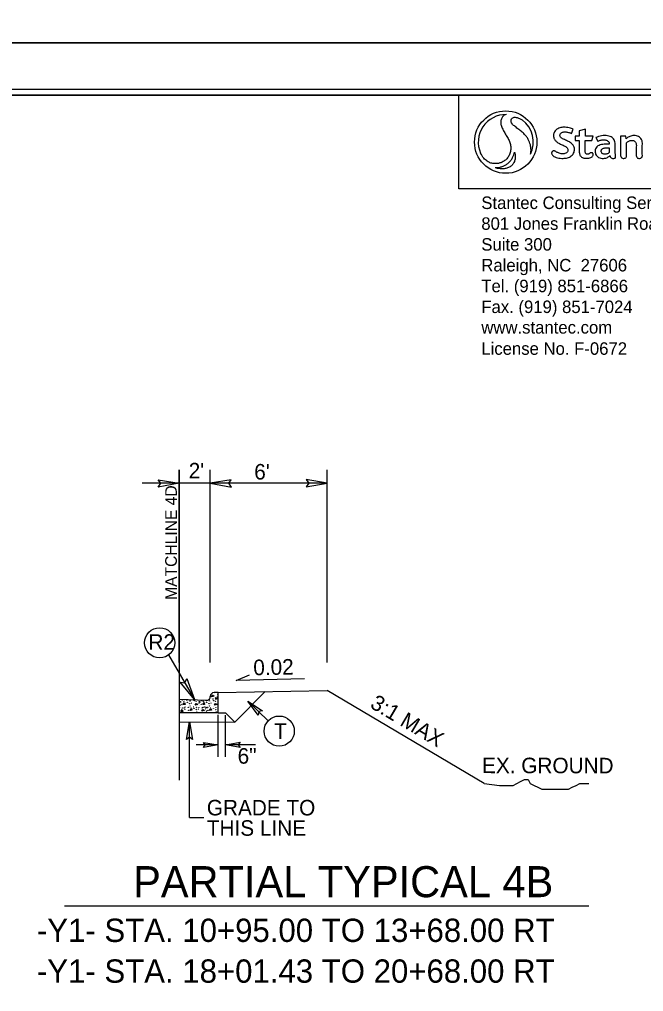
# Model space of a CAD drawing. Extents: x 2320980 to 2456309, y 595047 to 606177.
# Drawn here: x 2455941.7 to 2455995.1, y 596660.3 to 596743.6 of the extents above; entities that cross this region are included whole.
import ezdxf

# ---------------------------------------------------------------- set-up
doc = ezdxf.new("R2010")
doc.units = 0
for name, color, linetype in [('Matchline', 7, 'Continuous'), ('Matchline Text', 7, 'Continuous'), ('Old_Level_1', 7, 'Continuous'), ('Old_Level_2', 7, 'Continuous'), ('Old_Level_20', 7, 'Continuous'), ('Old_Level_21', 7, 'Continuous'), ('Old_Level_3', 7, 'Continuous'), ('Prop Dimension Text', 7, 'Continuous'), ('Scratch_Level_0', 7, 'Continuous'), ('Sheet Data Text CELL', 7, 'Continuous'), ('Sheet Plan CELL', 7, 'Continuous'), ('Sheet Plot Border Inside CELL', 7, 'Continuous'), ('Sheet Plot Border Outside CELL', 7, 'Continuous'), ('Typical Berm CELL', 7, 'Continuous'), ('Typical Curb CELL', 7, 'Continuous'), ('Typical Hinge Slope Arterial CELL', 7, 'Continuous'), ('Typical ID Circle CELL', 7, 'Continuous'), ('Typical Pavement Slope CELL', 7, 'Continuous'), ('Typical Terminator CELL', 7, 'Continuous')]:
    doc.layers.add(name, color=color, linetype=linetype)

msp = doc.modelspace()

# ---------------------------------------------------------------- linework, layer by layer
at = {"layer": 'Matchline'}
msp.add_line((2455955.368, 596705.007), (2455955.368, 596678.433), dxfattribs=at)
at = {"layer": 'Old_Level_21'}
for p, q in [((2455955.368, 596688.514), (2455955.368, 596705.007)), ((2455958.028, 596688.514), (2455958.028, 596705.007)), ((2455968.028, 596688.514), (2455968.028, 596705.007)), ((2455955.368, 596703.855), (2455952.191, 596703.855)), ((2455968.028, 596703.855), (2455955.368, 596703.855)), ((2455981.492, 596678.15), (2455968.028, 596686.124)), ((2455958.693, 596680.445), (2455958.693, 596684.035)), ((2455959.326, 596680.445), (2455959.326, 596683.989)), ((2455956.236, 596675.229), (2455957.475, 596675.229))]:
    msp.add_line(p, q, dxfattribs=at)
at = {"layer": 'Old_Level_3'}
msp.add_line((2455945.536, 596667.68), (2455990.456, 596667.68), dxfattribs=at)
at = {"layer": 'Prop Dimension Text'}
for p, q in [((2455962.993, 596683.528), (2455961.234, 596685.209)), ((2455956.236, 596675.229), (2455956.236, 596683.418)), ((2455958.693, 596681.457), (2455956.806, 596681.457)), ((2455961.888, 596681.457), (2455959.326, 596681.457))]:
    msp.add_line(p, q, dxfattribs=at)
msp.add_lwpolyline([(2455966.091, 596687.116), (2455960.235, 596686.955), (2455961.372, 596687.444)], dxfattribs=at)
for centre in [(2455953.687, 596690.196), (2455963.927, 596682.635)]:
    msp.add_circle(centre, 1.293, dxfattribs=at)
at = {"layer": 'Scratch_Level_0'}
msp.add_lwpolyline([(2455979.323, 596737.076), (2456002.097, 596737.079), (2456002.098, 596729.07), (2455979.324, 596729.067)], close=True, dxfattribs=at)
at = {"layer": 'Sheet Data Text CELL'}
for p, q in [((2455988.965, 596733.819), (2455989.095, 596734.192)), ((2455990.145, 596734.169), (2455989.619, 596734.022)), ((2455990.145, 596733.585), (2455990.145, 596734.169)), ((2455989.619, 596733.585), (2455989.285, 596733.585)), ((2455989.285, 596733.585), (2455989.285, 596733.219)), ((2455989.619, 596734.022), (2455989.619, 596733.585)), ((2455990.826, 596733.585), (2455990.145, 596733.585)), ((2455990.699, 596733.219), (2455990.826, 596733.585)), ((2455991.046, 596733.451), (2455991.206, 596733.141)), ((2455993.606, 596733.584), (2455993.163, 596733.584)), ((2455993.163, 596733.584), (2455993.163, 596731.906)), ((2455993.635, 596733.362), (2455993.606, 596733.584)), ((2455989.285, 596733.219), (2455989.623, 596733.219)), ((2455990.135, 596732.294), (2455990.142, 596733.219)), ((2455990.142, 596733.219), (2455990.699, 596733.219)), ((2455992.195, 596732.591), (2455992.196, 596732.176)), ((2455993.679, 596731.906), (2455993.679, 596733.014))]:
    msp.add_line(p, q, dxfattribs=at)
for points in [[(2455983.379, 596735.428), (2455983.379, 596735.428)], [(2455984.732, 596734.965), (2455984.732, 596734.965)]]:
    msp.add_lwpolyline(points, dxfattribs=at)
msp.add_circle((2455983.328, 596733.072), 2.673, dxfattribs=at)
for start, end in [(88.77376, 203.69163), (88.76731, 88.77376), (333.78865, 53.43978), (247.12556, 251.46513)]:
    msp.add_arc((2455983.328, 596733.072), 2.357, start, end, dxfattribs=at)
for points, degree in [([(2455983.379, 596735.428), (2455983.322, 596735.416), (2455983.188, 596735.388), (2455983.013, 596735.209), (2455982.883, 596734.916), (2455982.9, 596734.587), (2455983.016, 596734.269), (2455983.192, 596733.96), (2455983.374, 596733.619), (2455983.576, 596733.297), (2455983.716, 596732.97), (2455983.782, 596732.614), (2455983.739, 596732.258), (2455983.635, 596731.931), (2455983.434, 596731.634), (2455983.17, 596731.423), (2455982.894, 596731.299), (2455982.644, 596731.222), (2455982.365, 596731.222), (2455982.055, 596731.265), (2455981.749, 596731.405), (2455981.423, 596731.681), (2455981.266, 596731.952), (2455981.17, 596732.125)], 3), ([(2455983.379, 596735.428), (2455983.379, 596735.428), (2455983.379, 596735.428), (2455983.379, 596735.428)], 2), ([(2455985.442, 596732.031), (2455985.463, 596732.114), (2455985.498, 596732.269), (2455985.491, 596732.518), (2455985.467, 596732.737), (2455985.403, 596732.94), (2455985.327, 596733.175), (2455985.194, 596733.43), (2455985.004, 596733.67), (2455984.756, 596733.923), (2455984.446, 596734.148), (2455984.127, 596734.409), (2455983.871, 596734.601), (2455983.781, 596734.827), (2455983.78, 596734.999), (2455983.865, 596735.115), (2455983.978, 596735.196), (2455984.129, 596735.21), (2455984.307, 596735.176), (2455984.513, 596735.089), (2455984.655, 596735.009), (2455984.732, 596734.965)], 3), ([(2455989.095, 596734.192), (2455989.072, 596734.203), (2455988.968, 596734.253), (2455988.77, 596734.305), (2455988.527, 596734.335), (2455988.306, 596734.346), (2455988.121, 596734.328), (2455987.945, 596734.291), (2455987.775, 596734.224), (2455987.611, 596734.111), (2455987.493, 596733.961), (2455987.426, 596733.809), (2455987.411, 596733.667), (2455987.418, 596733.536), (2455987.446, 596733.411), (2455987.499, 596733.308), (2455987.563, 596733.215), (2455987.642, 596733.13), (2455987.738, 596733.053), (2455987.856, 596732.982), (2455988.003, 596732.906), (2455988.165, 596732.832), (2455988.33, 596732.762), (2455988.466, 596732.692), (2455988.566, 596732.607), (2455988.635, 596732.527), (2455988.659, 596732.429), (2455988.656, 596732.336), (2455988.618, 596732.233), (2455988.533, 596732.148), (2455988.398, 596732.09), (2455988.238, 596732.066), (2455988.06, 596732.074), (2455987.903, 596732.107), (2455987.776, 596732.17), (2455987.673, 596732.212), (2455987.604, 596732.277), (2455987.538, 596732.302), (2455987.478, 596732.328), (2455987.413, 596732.324), (2455987.348, 596732.304), (2455987.293, 596732.256), (2455987.257, 596732.188), (2455987.254, 596732.113), (2455987.265, 596732.039), (2455987.323, 596731.961), (2455987.435, 596731.849), (2455987.633, 596731.752), (2455987.878, 596731.687), (2455988.127, 596731.674), (2455988.341, 596731.68), (2455988.528, 596731.704), (2455988.692, 596731.754), (2455988.863, 596731.831), (2455989.027, 596731.96), (2455989.154, 596732.12), (2455989.208, 596732.309), (2455989.215, 596732.479), (2455989.194, 596732.633), (2455989.133, 596732.757), (2455989.06, 596732.881), (2455988.932, 596732.986), (2455988.787, 596733.083), (2455988.627, 596733.16), (2455988.454, 596733.241), (2455988.274, 596733.318), (2455988.121, 596733.399), (2455988.018, 596733.492), (2455987.974, 596733.583), (2455987.966, 596733.678), (2455987.994, 596733.765), (2455988.053, 596733.841), (2455988.135, 596733.895), (2455988.243, 596733.934), (2455988.372, 596733.944), (2455988.5, 596733.939), (2455988.627, 596733.919), (2455988.75, 596733.892), (2455988.865, 596733.858), (2455988.934, 596733.831), (2455988.965, 596733.819)], 3), ([(2455992.247, 596731.915), (2455992.248, 596731.897), (2455992.252, 596731.854), (2455992.295, 596731.79), (2455992.357, 596731.718), (2455992.469, 596731.666), (2455992.587, 596731.67), (2455992.697, 596731.694), (2455992.74, 596731.781), (2455992.742, 596731.868), (2455992.717, 596731.985), (2455992.69, 596732.307), (2455992.71, 596732.647), (2455992.704, 596733.015), (2455992.662, 596733.193), (2455992.562, 596733.353), (2455992.454, 596733.476), (2455992.276, 596733.566), (2455992.056, 596733.623), (2455991.795, 596733.64), (2455991.531, 596733.614), (2455991.277, 596733.555), (2455991.121, 596733.485), (2455991.046, 596733.451)], 3), ([(2455993.679, 596733.014), (2455993.687, 596733.022), (2455993.723, 596733.055), (2455993.809, 596733.107), (2455993.921, 596733.181), (2455994.063, 596733.224), (2455994.207, 596733.223), (2455994.346, 596733.178), (2455994.441, 596733.079), (2455994.493, 596732.961), (2455994.52, 596732.801), (2455994.503, 596732.562), (2455994.515, 596732.259), (2455994.499, 596732.006), (2455994.51, 596731.832), (2455994.57, 596731.738), (2455994.675, 596731.672), (2455994.797, 596731.674), (2455994.913, 596731.702), (2455995.008, 596731.774), (2455995.035, 596731.912), (2455995.015, 596732.156), (2455995.028, 596732.456), (2455995.021, 596732.786), (2455995.033, 596732.996), (2455995.005, 596733.178), (2455994.948, 596733.306), (2455994.857, 596733.437), (2455994.711, 596733.54), (2455994.527, 596733.627), (2455994.317, 596733.632), (2455994.128, 596733.621), (2455993.958, 596733.565), (2455993.807, 596733.495), (2455993.706, 596733.415), (2455993.653, 596733.375), (2455993.635, 596733.362)], 3), ([(2455989.623, 596733.219), (2455989.621, 596732.892), (2455989.62, 596732.547), (2455989.624, 596732.162), (2455989.641, 596732.07), (2455989.677, 596731.944), (2455989.749, 596731.858), (2455989.821, 596731.791), (2455989.898, 596731.74), (2455990.02, 596731.698), (2455990.188, 596731.679), (2455990.362, 596731.687), (2455990.536, 596731.711), (2455990.668, 596731.778), (2455990.765, 596731.856), (2455990.81, 596731.946), (2455990.815, 596732.025), (2455990.801, 596732.092), (2455990.766, 596732.131), (2455990.724, 596732.156), (2455990.675, 596732.165), (2455990.623, 596732.166), (2455990.57, 596732.152), (2455990.523, 596732.114), (2455990.47, 596732.074), (2455990.405, 596732.046), (2455990.336, 596732.024), (2455990.264, 596732.032), (2455990.202, 596732.066), (2455990.154, 596732.114), (2455990.133, 596732.197), (2455990.134, 596732.256), (2455990.135, 596732.294)], 3), ([(2455992.194, 596732.901), (2455992.16, 596732.9), (2455992.05, 596732.898), (2455991.859, 596732.889), (2455991.632, 596732.877), (2455991.42, 596732.83), (2455991.224, 596732.749), (2455991.053, 596732.602), (2455990.973, 596732.394), (2455990.984, 596732.198), (2455991.016, 596732.03), (2455991.118, 596731.888), (2455991.266, 596731.758), (2455991.478, 596731.679), (2455991.698, 596731.676), (2455991.902, 596731.702), (2455992.057, 596731.757), (2455992.172, 596731.835), (2455992.22, 596731.887), (2455992.247, 596731.915)], 3), ([(2455991.206, 596733.141), (2455991.23, 596733.154), (2455991.303, 596733.193), (2455991.422, 596733.23), (2455991.566, 596733.267), (2455991.702, 596733.276), (2455991.844, 596733.271), (2455991.972, 596733.231), (2455992.083, 596733.167), (2455992.161, 596733.074), (2455992.194, 596732.979), (2455992.194, 596732.92), (2455992.194, 596732.901)], 3), ([(2455992.196, 596732.176), (2455992.183, 596732.165), (2455992.134, 596732.128), (2455992.045, 596732.08), (2455991.92, 596732.028), (2455991.787, 596732.02), (2455991.672, 596732.05), (2455991.592, 596732.102), (2455991.54, 596732.163), (2455991.505, 596732.237), (2455991.5, 596732.316), (2455991.515, 596732.395), (2455991.562, 596732.47), (2455991.643, 596732.518), (2455991.739, 596732.561), (2455991.866, 596732.578), (2455991.996, 596732.585), (2455992.111, 596732.592), (2455992.171, 596732.591), (2455992.195, 596732.591)], 3), ([(2455982.412, 596730.901), (2455982.47, 596730.895), (2455982.606, 596730.882), (2455982.84, 596730.927), (2455983.101, 596730.988), (2455983.336, 596731.125), (2455983.552, 596731.277), (2455983.755, 596731.495), (2455983.923, 596731.737), (2455984.03, 596731.99), (2455984.062, 596732.139), (2455984.078, 596732.21)], 3), ([(2455984.078, 596732.21), (2455984.095, 596732.15), (2455984.139, 596731.997), (2455984.15, 596731.741), (2455984.106, 596731.463), (2455983.963, 596731.211), (2455983.771, 596730.979), (2455983.491, 596730.852), (2455983.194, 596730.784), (2455982.888, 596730.779), (2455982.679, 596730.819), (2455982.579, 596730.838)], 3), ([(2455993.163, 596731.906), (2455993.168, 596731.884), (2455993.179, 596731.834), (2455993.216, 596731.749), (2455993.31, 596731.677), (2455993.441, 596731.676), (2455993.573, 596731.686), (2455993.651, 596731.772), (2455993.679, 596731.847), (2455993.679, 596731.888), (2455993.679, 596731.906)], 3)]:
    msp.add_open_spline(points, degree=degree, dxfattribs=at)
at = {"layer": 'Sheet Plan CELL'}
for points in [[(2455742.104, 596527.076), (2455742.099, 596737.071), (2456002.097, 596737.079), (2456002.099, 596707.066), (2456042.107, 596707.064), (2456042.107, 596527.076)], [(2456042.112, 596737.076), (2455742.104, 596737.076), (2455742.104, 596527.076), (2456042.107, 596527.076)]]:
    msp.add_lwpolyline(points, close=True, dxfattribs=at)
at = {"layer": 'Sheet Plot Border Inside CELL'}
msp.add_lwpolyline([(2455711.407, 596526.574), (2456044.604, 596526.576), (2456044.607, 596737.574), (2455711.407, 596737.574)], close=True, dxfattribs=at)
at = {"layer": 'Sheet Plot Border Outside CELL'}
for points in [[(2455708.807, 596741.574), (2456045.507, 596741.574), (2456045.507, 596960.574), (2455708.807, 596960.574)], [(2455708.807, 596522.574), (2456045.507, 596522.574), (2456045.507, 596741.574), (2455708.807, 596741.574)]]:
    msp.add_lwpolyline(points, close=True, dxfattribs=at)
at = {"layer": 'Typical Berm CELL'}
for p, q in [((2455958.693, 596685.929), (2455968.028, 596686.124)), ((2455958.693, 596684.213), (2455959.316, 596684.213))]:
    msp.add_line(p, q, dxfattribs=at)
at = {"layer": 'Typical Curb CELL'}
for p, q in [((2455958.693, 596685.929), (2455958.347, 596685.929)), ((2455958.693, 596684.213), (2455958.693, 596685.929)), ((2455955.368, 596685.375), (2455957.696, 596685.278)), ((2455955.715, 596684.918), (2455955.83, 596685.077)), ((2455955.83, 596685.077), (2455955.875, 596684.926)), ((2455957.377, 596684.918), (2455957.491, 596685.077)), ((2455957.491, 596685.077), (2455957.536, 596684.926)), ((2455958.028, 596685.597), (2455958.028, 596685.611)), ((2455958.142, 596685.577), (2455958.225, 596685.729)), ((2455958.362, 596685.63), (2455958.142, 596685.577)), ((2455958.225, 596685.729), (2455958.362, 596685.63)), ((2455958.439, 596685.486), (2455958.462, 596685.365)), ((2455958.644, 596685.426), (2455958.439, 596685.486)), ((2455958.462, 596685.365), (2455958.644, 596685.426)), ((2455958.693, 596684.213), (2455955.368, 596684.213)), ((2455955.503, 596684.317), (2455955.618, 596684.476)), ((2455955.664, 596684.326), (2455955.503, 596684.317)), ((2455955.618, 596684.476), (2455955.664, 596684.326)), ((2455955.875, 596684.926), (2455955.715, 596684.918)), ((2455956.292, 596684.409), (2455956.407, 596684.568)), ((2455956.453, 596684.417), (2455956.292, 596684.409)), ((2455956.407, 596684.568), (2455956.453, 596684.417)), ((2455956.733, 596684.85), (2455956.816, 596685.003)), ((2455956.953, 596684.903), (2455956.733, 596684.85)), ((2455956.816, 596685.003), (2455956.953, 596684.903)), ((2455957.311, 596684.341), (2455957.394, 596684.493)), ((2455957.531, 596684.394), (2455957.311, 596684.341)), ((2455957.536, 596684.926), (2455957.377, 596684.918)), ((2455957.394, 596684.493), (2455957.531, 596684.394)), ((2455957.955, 596684.409), (2455958.068, 596684.568)), ((2455958.114, 596684.417), (2455957.955, 596684.409)), ((2455958.068, 596684.568), (2455958.114, 596684.417)), ((2455958.394, 596684.85), (2455958.477, 596685.003)), ((2455958.614, 596684.903), (2455958.394, 596684.85)), ((2455958.477, 596685.003), (2455958.614, 596684.903))]:
    msp.add_line(p, q, dxfattribs=at)
for centre in [(2455955.39, 596685.048), (2455955.413, 596685.177), (2455955.488, 596685.131), (2455955.632, 596685.297), (2455955.761, 596685.184), (2455955.822, 596685.32), (2455956.019, 596685.236), (2455956.057, 596685.101), (2455956.293, 596685.215), (2455956.315, 596685.282), (2455956.422, 596685.025), (2455956.657, 596685.244), (2455956.657, 596685.244), (2455956.816, 596685.177), (2455957.052, 596685.048), (2455957.074, 596685.177), (2455957.149, 596685.131), (2455957.293, 596685.241), (2455957.422, 596685.184), (2455957.681, 596685.236), (2455957.718, 596685.101), (2455957.954, 596685.215), (2455957.976, 596685.282), (2455958.083, 596685.025), (2455958.101, 596685.456), (2455958.26, 596685.388), (2455958.318, 596685.244), (2455958.387, 596685.828), (2455958.478, 596685.177), (2455958.607, 596685.54), (2455958.675, 596685.783), (2455955.383, 596684.638), (2455955.466, 596684.858), (2455955.587, 596684.539), (2455955.594, 596684.919), (2455955.662, 596684.607), (2455955.822, 596684.622), (2455955.846, 596684.5), (2455955.875, 596684.698), (2455956.148, 596684.668), (2455956.172, 596684.409), (2455956.255, 596684.987), (2455956.3, 596684.782), (2455956.376, 596684.63), (2455956.611, 596684.714), (2455956.611, 596684.714), (2455956.635, 596684.592), (2455956.635, 596684.592), (2455956.832, 596684.478), (2455956.839, 596684.661), (2455956.878, 596684.273), (2455956.999, 596684.516), (2455957.044, 596684.638), (2455957.128, 596684.858), (2455957.255, 596684.919), (2455957.324, 596684.607), (2455957.394, 596684.667), (2455957.536, 596684.698), (2455957.629, 596684.539), (2455957.652, 596684.667), (2455957.705, 596684.349), (2455957.727, 596684.622), (2455957.809, 596684.668), (2455957.833, 596684.409), (2455957.916, 596684.987), (2455957.961, 596684.782), (2455958.037, 596684.63), (2455958.273, 596684.714), (2455958.296, 596684.592), (2455958.494, 596684.478), (2455958.5, 596684.661), (2455958.539, 596684.273), (2455958.661, 596684.516)]:
    msp.add_circle(centre, 0.0107, dxfattribs=at)
for centre, start, end in [((2455958.347, 596685.611), 90, 180), ((2455957.709, 596685.597), 267.61554, 360)]:
    msp.add_arc(centre, 0.319, start, end, dxfattribs=at)
at = {"layer": 'Typical Hinge Slope Arterial CELL'}
msp.add_lwpolyline([(2455981.492, 596678.15), (2455982.802, 596677.986), (2455983.13, 596677.986), (2455983.622, 596677.986), (2455983.95, 596677.986), (2455984.278, 596678.15), (2455984.605, 596678.314), (2455984.933, 596678.479), (2455985.261, 596678.479), (2455985.425, 596678.15), (2455985.753, 596677.986), (2455986.08, 596677.822), (2455986.408, 596677.659), (2455986.736, 596677.659), (2455987.063, 596677.659), (2455987.391, 596677.659), (2455987.719, 596677.659), (2455988.046, 596677.659), (2455988.374, 596677.659), (2455988.702, 596677.659), (2455989.029, 596677.822), (2455989.357, 596677.986), (2455989.685, 596678.15), (2455990.177, 596678.15), (2455990.448, 596678.15)], dxfattribs=at)
at = {"layer": 'Typical ID Circle CELL'}
msp.add_line((2455954.459, 596689.158), (2455956.683, 596685.342), dxfattribs=at)
at = {"layer": 'Typical Pavement Slope CELL'}
for p in [(2455962.734, 596686.014), (2455959.316, 596684.213), (2455955.368, 596683.421)]:
    msp.add_line(p, (2455960.125, 596683.404), dxfattribs=at)
at = {"layer": 'Typical Terminator CELL'}
for points in [[(2455966.233, 596703.546), (2455968.028, 596703.855), (2455966.223, 596704.174), (2455966.452, 596703.855)], [(2455953.573, 596704.164), (2455955.368, 596703.855), (2455953.563, 596703.536), (2455953.792, 596703.855)], [(2455959.824, 596704.164), (2455958.028, 596703.855), (2455959.834, 596703.536), (2455959.605, 596703.855)], [(2455956.011, 596687.144), (2455956.683, 596685.342), (2455955.432, 596686.819), (2455955.845, 596686.779)], [(2455962.137, 596683.989), (2455961.234, 596685.209), (2455962.505, 596684.361), (2455962.183, 596684.301)], [(2455955.978, 596681.921), (2455956.236, 596683.418), (2455956.501, 596681.913), (2455956.235, 596682.104)], [(2455957.446, 596681.672), (2455958.693, 596681.457), (2455957.439, 596681.236), (2455957.599, 596681.457)], [(2455960.573, 596681.243), (2455959.326, 596681.457), (2455960.58, 596681.679), (2455960.42, 596681.457)]]:
    msp.add_lwpolyline(points, close=True, dxfattribs=at)

# ---------------------------------------------------------------- texts
at = {"layer": 'Matchline Text'}
msp.add_text('MATCHLINE 4D', height=1, rotation=90, dxfattribs=at).set_placement((2455955.163, 596693.872))
at = {"layer": 'Old_Level_1'}
msp.add_text('EX. GROUND', height=1.33, rotation=359.91026, dxfattribs=at).set_placement((2455981.296, 596679.035))
at = {"layer": 'Old_Level_2'}
for s, height, p in [('PARTIAL TYPICAL 4B', 2.66, (2455951.42, 596668.413)), ('-Y1- STA. 10+95.00 TO 13+68.00 RT', 1.995, (2455943.176, 596664.581)), ('-Y1- STA. 18+01.43 TO 20+68.00 RT', 1.995, (2455943.176, 596661.09))]:
    msp.add_text(s, height=height, dxfattribs=at).set_placement(p)
at = {"layer": 'Old_Level_20'}
for s, p in [('R2', (2455952.727, 596689.597)), ('T', (2455963.49, 596681.97))]:
    msp.add_text(s, height=1.33, dxfattribs=at).set_placement(p)
at = {"layer": 'Old_Level_21'}
for s, rotation, p in [("2'", 0.00016, (2455956.174, 596704.272)), ('0.02', 1.14561, (2455961.721, 596687.416)), ('3:1 MAX', 329.36155, (2455971.628, 596684.694))]:
    msp.add_text(s, height=1.33, rotation=rotation, dxfattribs=at).set_placement(p)
for s, p in [("6'", (2455961.787, 596704.178)), ('6"', (2455960.365, 596679.846)), ('GRADE TO', (2455957.729, 596675.415)), ('THIS LINE', (2455957.729, 596673.672))]:
    msp.add_text(s, height=1.33, dxfattribs=at).set_placement(p)
at = {"layer": 'Sheet Data Text CELL'}
for s, height, p in [('Stantec Consulting Services Inc.', 1.06932, (2455981.236, 596727.34)), ('801 Jones Franklin Road', 1.06932, (2455981.236, 596725.559)), ('Suite 300', 1.0693, (2455981.236, 596723.777)), ('Raleigh, NC  27606', 1.06932, (2455981.236, 596721.996)), ('Tel. (919) 851-6866', 1.06932, (2455981.237, 596720.215)), ('Fax. (919) 851-7024', 1.06932, (2455981.237, 596718.433)), ('www.stantec.com', 1.06932, (2455981.237, 596716.673)), ('License No. F-0672', 1.06932, (2455981.237, 596714.857))]:
    msp.add_text(s, height=height, rotation=0.00714, dxfattribs=at).set_placement(p)

doc.saveas('drawing.dxf')
